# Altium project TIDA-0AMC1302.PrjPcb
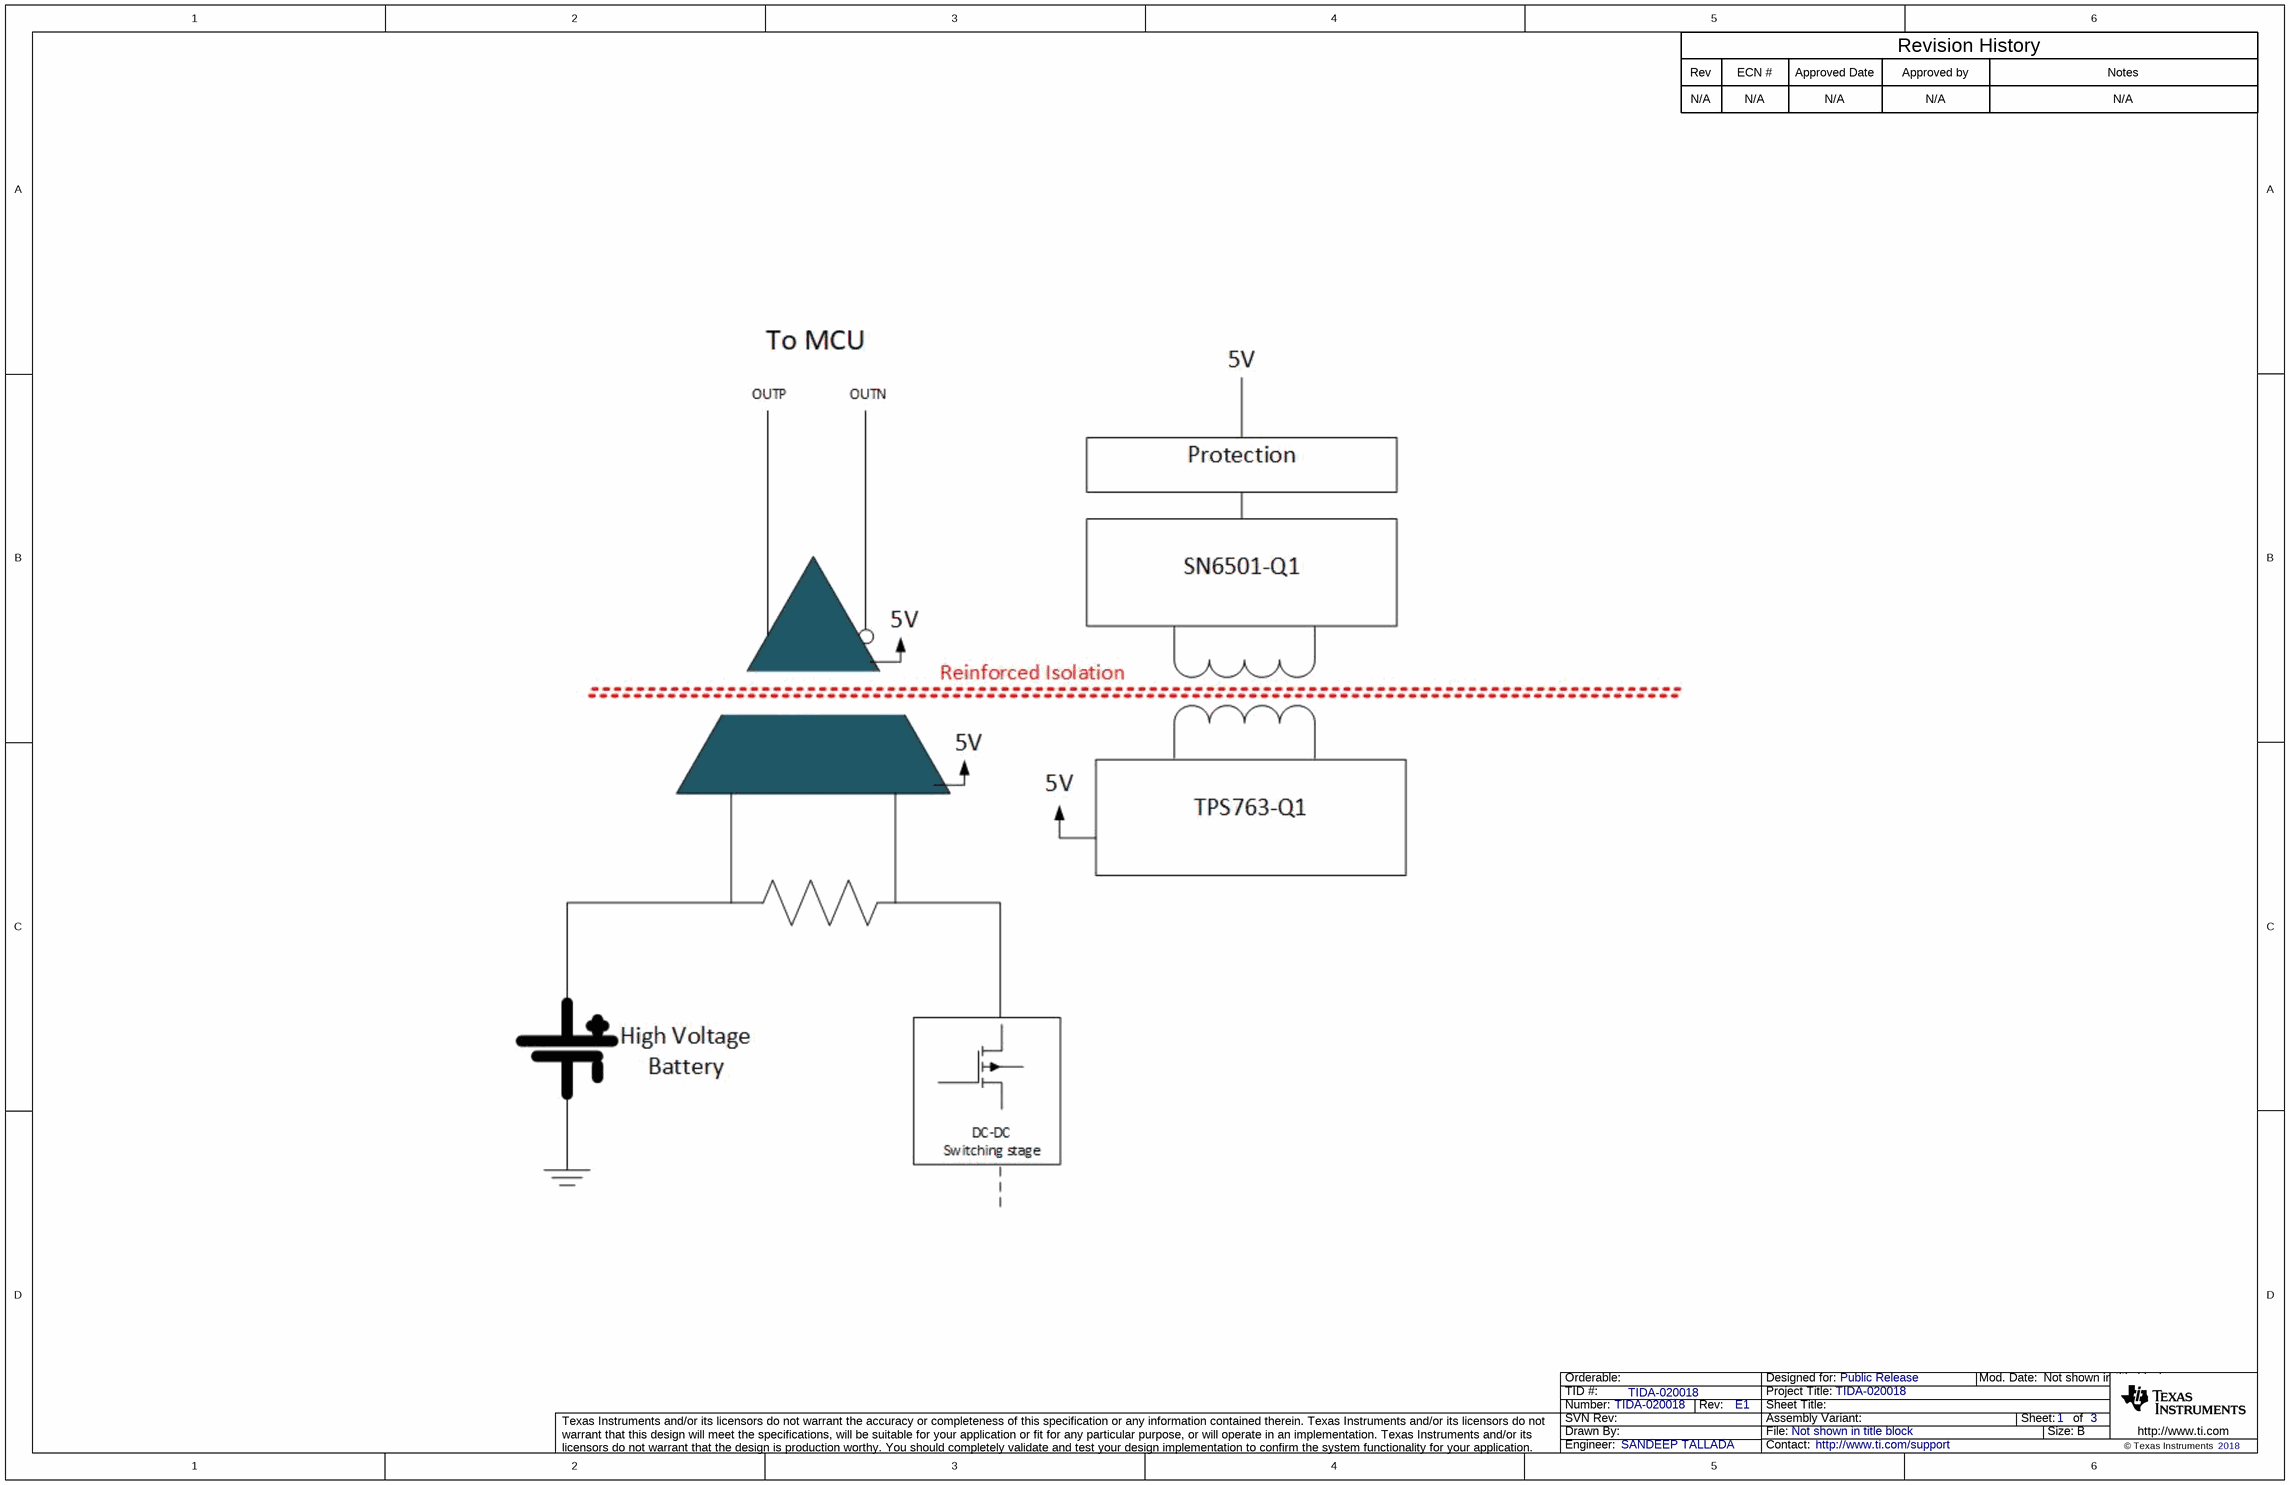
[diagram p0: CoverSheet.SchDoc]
TID: TIDA-020018; TechSupport: http://www.ti.com/support; SCH_Rev: E1; PRJ_Title: TIDA-020018; PRJ_Number: TIDA-020018; PRJ_Engineer: SANDEEP TALLADA; PRJ_Customer: Public Release; PCB_Rev: E1; PCB_Layout: Sandeep; CopyrightYear: 2018
3 sheets, 64 parts. Net scope: flat (ports and power ports of the same name join across sheets).
Board file: TIDA-0AMC1302.PcbDoc
Sheets:
  CoverSheet.SchDoc
  BlankSheet.SchDoc
  EVM_Hardware.SchDoc

## Sheet CoverSheet.SchDoc
size 431 x 279 mm; Date: Not shown in title block; ApprovedBy: Not shown in title block; CheckedBy: Not shown in title block; Author: Not shown in title block; CompanyName: Not shown in title block; Engineer: Not shown in title block; Organization: Not shown in title block; Address1: Not shown in title block; Address2: Not shown in title block; Address3: Not shown in title block; Address4: Not shown in title block; DocumentNumber: 1; Revision: Use project parameter SCH_Rev; SheetNumber: 1; SheetTotal: 3; PageSetup: Record=PageOptions¦CenterHorizontal=True¦CenterVertical=True¦PrintScale=1.00¦XCorrection=1.00¦YCorrection=1.00¦PrintKind=0¦BorderSize=5000000¦LeftOffset=0¦BottomOffset=0¦Orientation=2¦PaperLength=1000¦PaperWidth=1000¦Scale=100¦PaperSource=15¦PrintQuality=600¦MediaType=1¦DitherType=10¦PaperKind=Letter¦PrintScaleMode=1

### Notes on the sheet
- Rev
- N/A
- ECN #
- Approved Date
- Approved by
- Revision History
- Notes

## Sheet BlankSheet.SchDoc: TIDA-020018
size 431 x 279 mm; Date: Not shown in title block; ApprovedBy: Not shown in title block; CheckedBy: Not shown in title block; Author: Not shown in title block; CompanyName: Not shown in title block; Engineer: Sandeep Tallada; Organization: Not shown in title block; Address1: Not shown in title block; Address2: Not shown in title block; Address3: Not shown in title block; Address4: Not shown in title block; DocumentNumber: 1; Revision: Use project parameter SCH_Rev; SheetNumber: 2; SheetTotal: 3; PageSetup: Record=PageOptions¦CenterHorizontal=True¦CenterVertical=True¦PrintScale=1.00¦XCorrection=1.00¦YCorrection=1.00¦PrintKind=0¦BorderSize=5000000¦LeftOffset=0¦BottomOffset=0¦Orientation=2¦PaperLength=1000¦PaperWidth=1000¦Scale=100¦PaperSource=15¦PrintQuality=600¦MediaType=1¦DitherType=10¦PaperKind=Letter¦PrintScaleMode=1
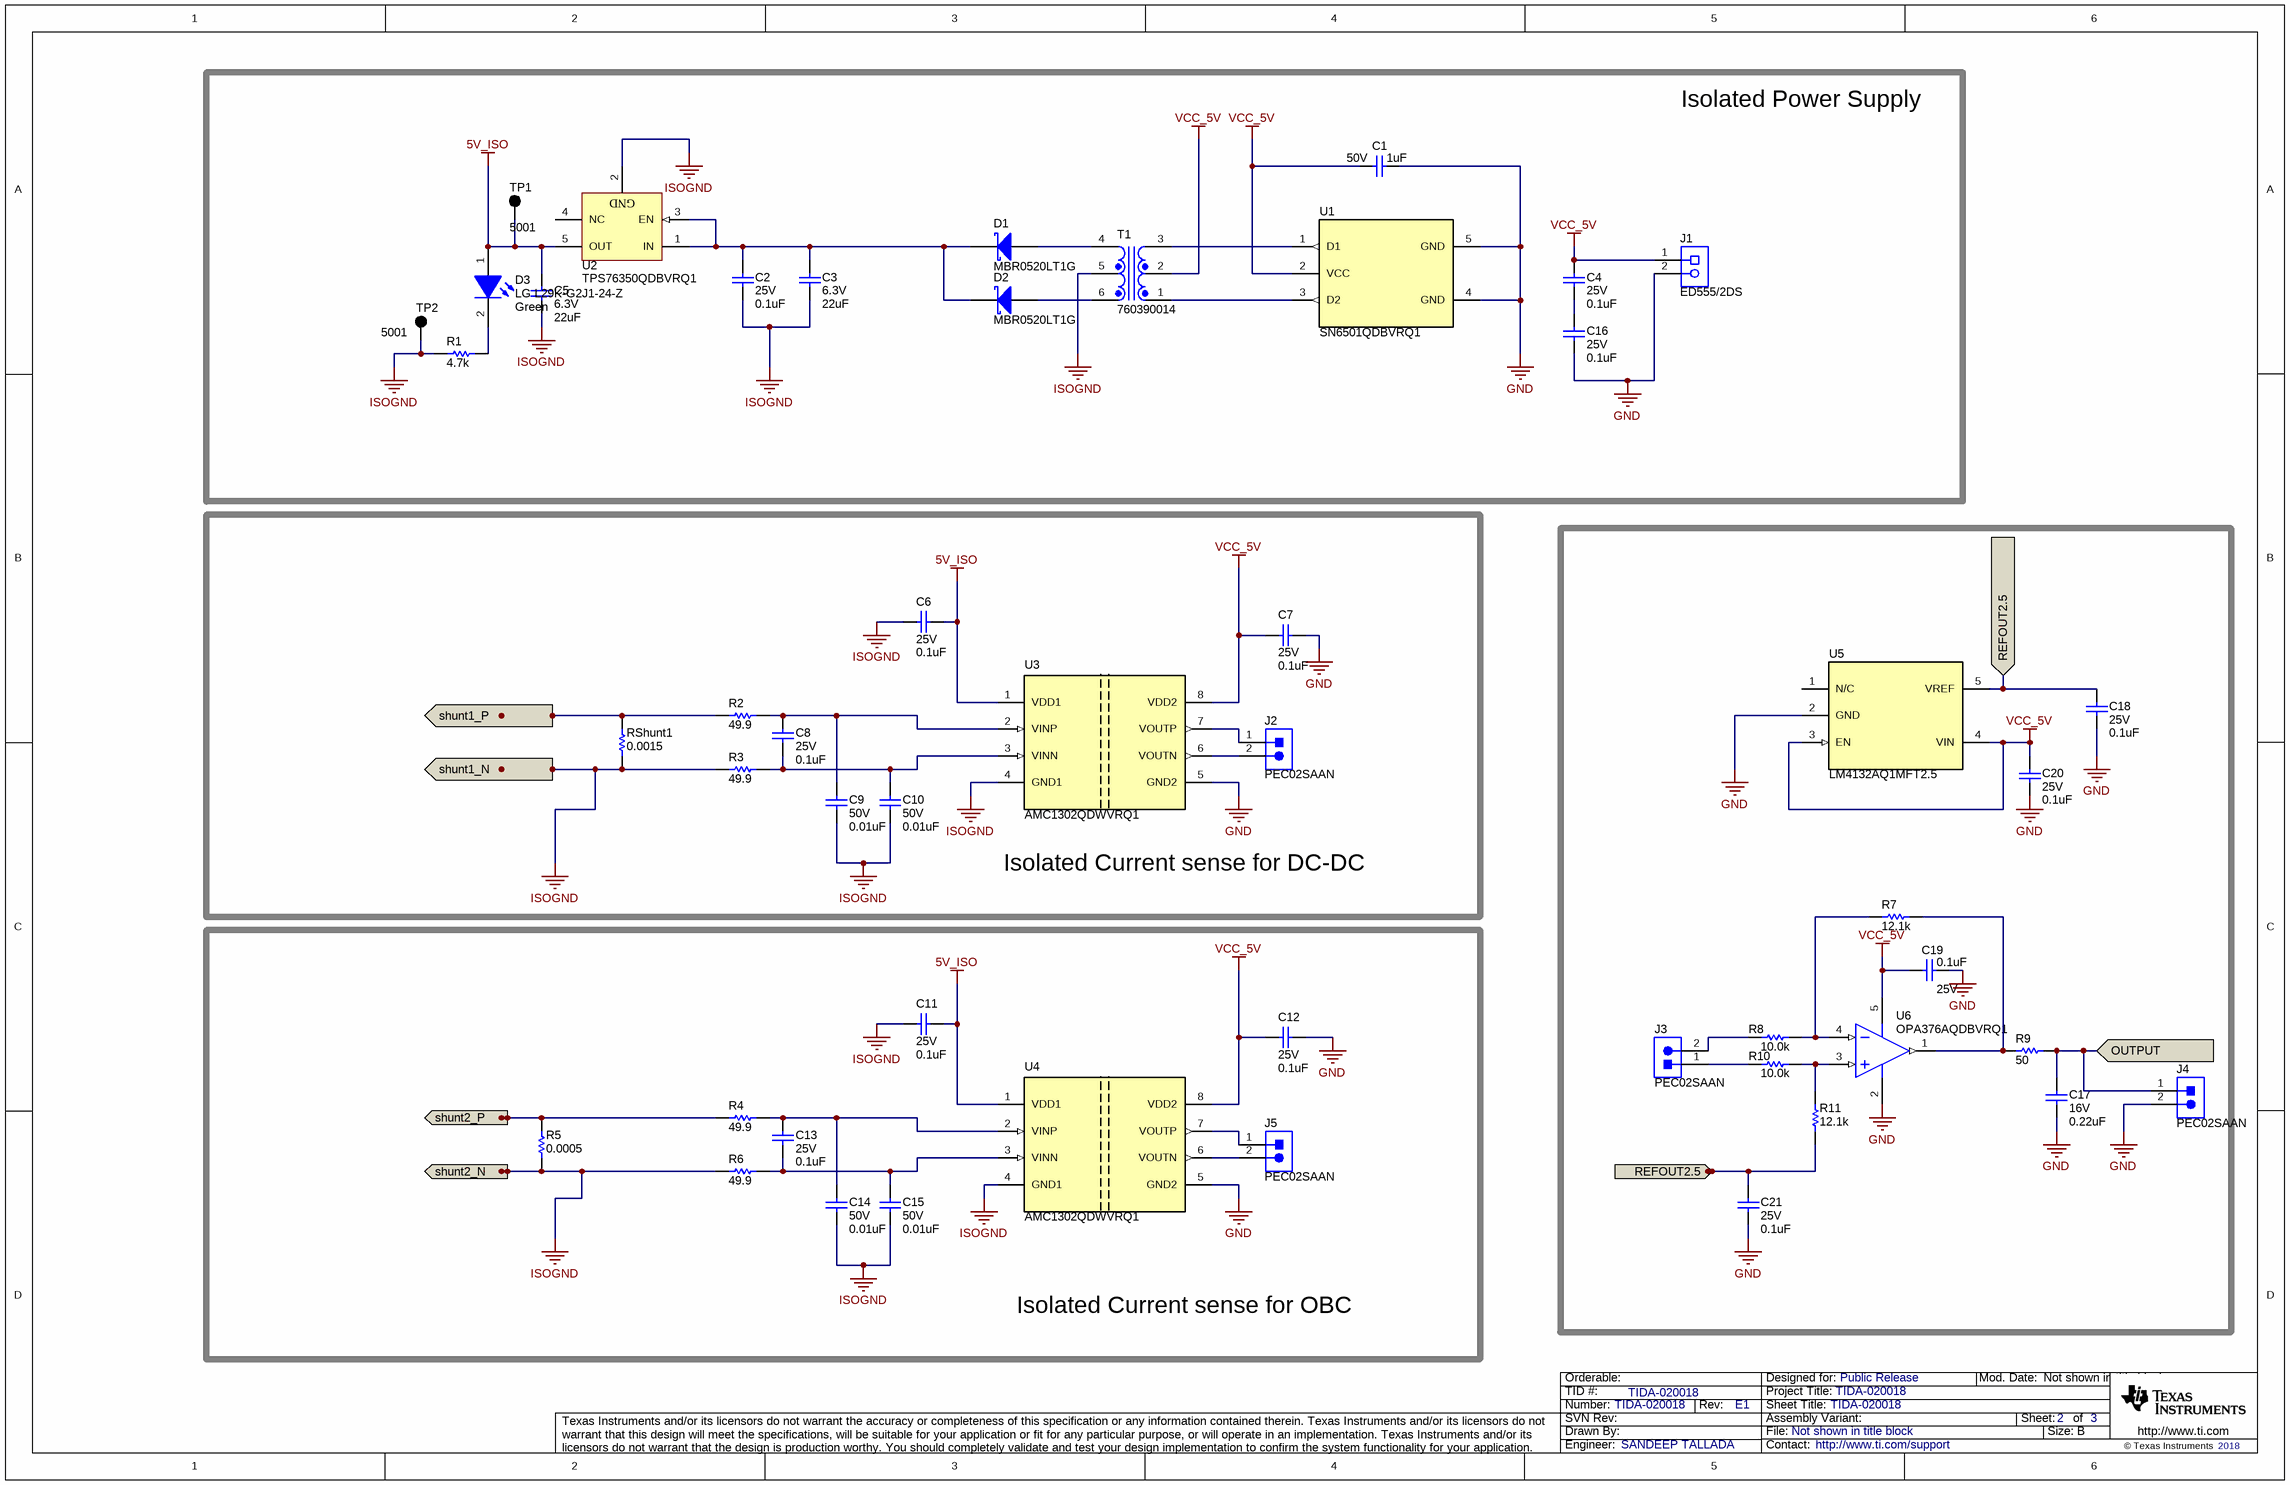
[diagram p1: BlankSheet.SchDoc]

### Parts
C1  VDC_V: 50V  ValueDisplayed: 1uF  [0603]  (hidden comment: UMK107AB7105KA-T)
C2  VDC_V: 25V  ValueDisplayed: 0.1uF  [0603]  (hidden comment: C1608X7R1E104K080AA)
C3  VDC_V: 6.3V  ValueDisplayed: 22uF  [0805_HV]  (hidden comment: JMK212BJ226MG-T)
C4  VDC_V: 25V  ValueDisplayed: 0.1uF  [0603]  (hidden comment: C1608X7R1E104K080AA)
C5  VDC_V: 6.3V  ValueDisplayed: 22uF  [0805_HV]  (hidden comment: JMK212BJ226MG-T)
C6  VDC_V: 25V  ValueDisplayed: 0.1uF  [0603]  (hidden comment: C1608X7R1E104K080AA)
C7  VDC_V: 25V  ValueDisplayed: 0.1uF  [0603]  (hidden comment: C1608X7R1E104K080AA)
C8  VDC_V: 25V  ValueDisplayed: 0.1uF  [0603]  (hidden comment: C1608X7R1E104K080AA)
C9  VDC_V: 50V  ValueDisplayed: 0.01uF  [0603]  (hidden comment: CL10B103KB8NCNC)
C10  VDC_V: 50V  ValueDisplayed: 0.01uF  [0603]  (hidden comment: CL10B103KB8NCNC)
C11  VDC_V: 25V  ValueDisplayed: 0.1uF  [0603]  (hidden comment: C1608X7R1E104K080AA)
C12  VDC_V: 25V  ValueDisplayed: 0.1uF  [0603]  (hidden comment: C1608X7R1E104K080AA)
C13  VDC_V: 25V  ValueDisplayed: 0.1uF  [0603]  (hidden comment: C1608X7R1E104K080AA)
C14  VDC_V: 50V  ValueDisplayed: 0.01uF  [0603]  (hidden comment: CL10B103KB8NCNC)
C15  VDC_V: 50V  ValueDisplayed: 0.01uF  [0603]  (hidden comment: CL10B103KB8NCNC)
C16  VDC_V: 25V  ValueDisplayed: 0.1uF  [0603]  (hidden comment: C1608X7R1E104K080AA)
C17  VDC_V: 16V  ValueDisplayed: 0.22uF  [0402]  (hidden comment: C1005X7R1C224K050BC)
C18  VDC_V: 25V  ValueDisplayed: 0.1uF  [0603]  (hidden comment: C1608X7R1E104K080AA)
C19  VDC_V: 25V  ValueDisplayed: 0.1uF  [0603]  (hidden comment: C1608X7R1E104K080AA)
C20  VDC_V: 25V  ValueDisplayed: 0.1uF  [0603]  (hidden comment: C1608X7R1E104K080AA)
C21  VDC_V: 25V  ValueDisplayed: 0.1uF  [0603]  (hidden comment: C1608X7R1E104K080AA)
D1  MBR0520LT1G  [SOD-123]
D2  MBR0520LT1G  [SOD-123]
D3  LG L29K-G2J1-24-Z  value Green  [LG L29K_GREEN]
J1  ED555/2DS  [TERM_BLK_ED555-2DS]
J2  PEC02SAAN  [CONN_PEC02SAAN]
J3  PEC02SAAN  [CONN_PEC02SAAN]
J4  PEC02SAAN  [CONN_PEC02SAAN]
J5  PEC02SAAN  [CONN_PEC02SAAN]
R1  ValueDisplayed: 4.7k  [0603]  (hidden comment: CRCW06034K70JNEA)
R2  ValueDisplayed: 49.9  [TNPW0603]  (hidden comment: TNPW060349R9BEEA)
R3  ValueDisplayed: 49.9  [TNPW0603]  (hidden comment: TNPW060349R9BEEA)
R4  ValueDisplayed: 49.9  [TNPW0603]  (hidden comment: TNPW060349R9BEEA)
R5  ValueDisplayed: 0.0005  [CSS2725_0005]  (hidden comment: CSS2725FTL500)
R6  ValueDisplayed: 49.9  [TNPW0603]  (hidden comment: TNPW060349R9BEEA)
R7  ValueDisplayed: 12.1k  [0402]  (hidden comment: ERA-2AEB1212X)
R8  ValueDisplayed: 10.0k  [0402]  (hidden comment: RT0402BRD0710KL)
R9  ValueDisplayed: 50  [0402]  (hidden comment: FC0402E50R0BST1)
R10  ValueDisplayed: 10.0k  [0402]  (hidden comment: RT0402BRD0710KL)
R11  ValueDisplayed: 12.1k  [0402]  (hidden comment: ERA-2AEB1212X)
RShunt1  ValueDisplayed: 0.0015  [2512_WIDE]  (hidden comment: PML100HZPJV1L5)
T1  760390014  [Wurth_760390013]
TP1  5001  [Keystone5001]
TP2  5001  [Keystone5001]
U1  SN6501QDBVRQ1  [DBV0005A_L]
U2  TPS76350QDBVRQ1  [DBV0005A_N]
U3  AMC1302QDWVRQ1  [DWV0008A]
U4  AMC1302QDWVRQ1  [DWV0008A]
U5  LM4132AQ1MFT2.5  [DBV0005A_N]
U6  OPA376AQDBVRQ1  [DBV0005A_N]

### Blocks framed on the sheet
Isolated Power Supply: C1-C5 C16 D1-D3 J1 R1 T1 TP1 TP2 U1 U2
Isolated Current sense for DC-DC: C6-C10 J2 R2 R3 RShunt1 U3
Isolated Current sense for OBC: C11-C15 J5 R4-R6 U4

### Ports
OUTPUT, REFOUT2.5, shunt1_N (in), shunt1_P (in), shunt2_N (in), shunt2_P (in)

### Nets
5V_ISO: C5.1 C6.2 C11.2 D3.1(A) TP1.1 U2.5(OUT) U3.1(VDD1) U4.1(VDD1)
GND: C1.1 C7.2 C12.2 C16.2 C17.2 C18.2 C19.1 C20.1 C21.2 J1.2 J4.2 U1.4(GND) U1.5(GND) U3.5(GND2) U4.5(GND2) U5.2(GND) U6.2(V-)
ISOGND: C2.2 C3.2 C5.2 C6.1 C9.2 C10.2 C11.1 C14.2 C15.2 R1.1 R3.1 R5.1 R6.1 RShunt1.1 T1.5 TP2.1 U2.2(GND) U3.4(GND1) U4.4(GND1) ; port shunt1_N, port shunt2_N
VCC_5V: C1.2 C4.1 C7.1 C12.1 C19.2 C20.2 J1.1 T1.2 U1.2(VCC) U3.8(VDD2) U4.8(VDD2) U5.3(EN) U5.4(VIN) U6.5(V+)
OUTPUT: C17.1 J4.1 R9.2 ; port OUTPUT
REFOUT2.5: C18.1 C21.1 R11.1 U5.5(VREF) ; port REFOUT2.5
shunt1_P: R2.1 RShunt1.2 ; port shunt1_P
shunt2_P: R4.1 R5.2 ; port shunt2_P
NetC2_1: C2.1 C3.1 D1.1(K) D2.1(K) U2.1(IN) U2.3(EN)
NetC4_2: C4.2 C16.1
NetC8_1: C8.1 C9.1 R2.2 U3.2(VINP)
NetC8_2: C8.2 C10.1 R3.2 U3.3(VINN)
NetC13_1: C13.1 C14.1 R4.2 U4.2(VINP)
NetC13_2: C13.2 C15.1 R6.2 U4.3(VINN)
NetD1_2: D1.2(A) T1.4
NetD2_2: D2.2(A) T1.6
NetD3_2: D3.2(K) R1.2
NetJ2_1: J2.1 U3.7(VOUTP)
NetJ2_2: J2.2 U3.6(VOUTN)
NetJ3_1: J3.1 R10.1
NetJ3_2: J3.2 R8.1
NetJ5_1: J5.1 U4.7(VOUTP)
NetJ5_2: J5.2 U4.6(VOUTN)
NetR7_1: R7.1 R8.2 U6.4(IN-)
NetR7_2: R7.2 R9.1 U6.1(OUT)
NetR10_2: R10.2 R11.2 U6.3(IN+)
NetT1_1: T1.1 U1.3(D2)
NetT1_3: T1.3 U1.1(D1)

Not connected (* = marked no-connect by the designer): U2 4(NC); U5 1(N/C)

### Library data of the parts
C1 = CMP-0007508-5: CAP, CERM, 1 uF, 50 V, +/- 10%, X7R, 0603; Manufacturer: Taiyo Yuden; TaMin_C: -55°C; Polarized: N; SizeAreaWB_mm2: 4.68; Value1: Unknown; U/M: EA; Value: 1uF; TaMax_C: 125°C; SizeZ_mm: 1; SizeX_mm: 1.6; SizeY_mm: 0.8; SizeArea_mm2: 1.28; Cap_F: 1µF; AEC Category: Q200
C2 C4 C6-C8 C11-C13 C16 C18-C21 = CMP-0007039-5: CAP, CERM, 0.1 uF, 25 V, +/- 10%, X7R, 0603; Manufacturer: TDK; TaMin_C: -55°C; Polarized: N; SizeAreaWB_mm2: 4.68; Value1: Unknown; U/M: EA; Value: 0.1uF; TaMax_C: 125°C; SizeZ_mm: 1; SizeX_mm: 1.6; SizeY_mm: 0.8; SizeArea_mm2: 1.28; Cap_F: 100nF; AEC Category: Q200
C3 C5 = CMP-0008391-2: CAP, CERM, 22 uF, 6.3 V, +/- 20%, X5R, 0805; Manufacturer: Taiyo Yuden; TaMin_C: -55°C; Polarized: N; SizeAreaWB_mm2: 6.75; Value1: Unknown; U/M: EA; Value: 22uF; TaMax_C: 85°C; SizeZ_mm: 1.45; SizeX_mm: 2; SizeY_mm: 1.25; Cap_Case: 0805; SizeArea_mm2: 2.5; Cap_F: 22µF; AEC Category: Q200
C9 C10 C14 = CMP-0007109-5: CAP, CERM, 0.01 uF, 50 V, +/- 10%, X7R, 0603; Manufacturer: Samsung Electro-Mechanics; TaMin_C: -55°C; Polarized: N; SizeAreaWB_mm2: 4.68; Value1: Unknown; U/M: EA; Value: 0.01uF; TaMax_C: 125°C; SizeZ_mm: 1; SizeX_mm: 1.6; SizeY_mm: 0.8; SizeArea_mm2: 1.28; Cap_F: 10nF; AEC Category: Q200
C15 = CMP-0007109-5: CAP, CERM, 0.01 uF, 50 V, +/- 10%, X7R, 0603; Manufacturer: Samsung Electro-Mechanics; TaMin_C: -55°C; Polarized: N; SizeAreaWB_mm2: 4.68; Value1: Unknown; U/M: EA; Value: 0.01uF; TaMax_C: 125°C; SizeZ_mm: 1; SizeX_mm: 1.6; SizeY_mm: 0.8; SizeArea_mm2: 1.28; CompType: Capacitor; Cap_F: 10nF; AEC Category: Q200
C17 = CMP-0006293-2: CAP, CERM, 0.22 uF, 16 V, +/- 10%, X7R, 0402; Manufacturer: TDK; TaMin_C: -55°C; Polarized: N; SizeAreaWB_mm2: 3; Value1: Unknown; U/M: EA; Value: 0.22uF; TaMax_C: 125°C; SizeZ_mm: 0.6; SizeX_mm: 1; SizeY_mm: 0.5; Cap_F: 220nF; AEC Category: Q200
D1 D2 = CMP-0028524-1: Diode, Schottky, 20 V, 0.5 A, SOD-123; Manufacturer: ON Semiconductor; Io_A: 5dA; Green_Lifecycle: Active; SizeAreaWB_mm2: 13.095; Vr_V: 20V; Green_REACh: Passed; Value1: 0.5A; TJmax_C: 125°C; U/M: EA; Value: 20V; SizeZ_mm: 1.35; SizeX_mm: 3.85; SizeY_mm: 1.7; Vf_V: 3.85dV; Value2: 0.385V; SizeArea_mm2: 6.545; AEC Category: Q101; RJC_CperW: 150
D3 = CMP-0002874-1: LED, Green, SMD; Manufacturer: OSRAM; Io_A: 2mA; Tjmax_C: 110°C; Value1: W; U/M: EA; Vf_V: 1.7V
J1 = CMP-0074913-1: Terminal Block, 3.5mm Pitch, 2x1, TH; Manufacturer: On-Shore Technology; Cert_VDE: Y; CNHeader: False; Current_A: 6A; Green_Lifecycle: Active; Shrouded: N; Gender: Female; Green_REACh: Passed; Voltage_V: 150V; Row_Count: 1; Pitch_mm: 3.5; ContactFinish: Brass; CT: True
J2-J5 = CMP-0002337-1: Header, 100mil, 2x1, Tin, TH; Manufacturer: Sullins Connector Solutions; CNHeader: TRUE; Current_A: 3A; Green_Lifecycle: Not Set; Shrouded: N; Gender: Male; Green_REACh: Incomplete; Voltage_V: 1.8kV; Row_Count: 1; Pitch_mm: 2.54; CT: FALSE; Cert_UL: Y
R1 = CMP-0025817-4: RES, 4.7 k, 5%, 0.1 W, AEC-Q200 Grade 0, 0603; Manufacturer: Vishay-Dale; Power_W: 100mW; TempCo: 200 ppm/C; Value_Code: 4k70; Value: 4.7k; EIA_Code: E24; SizeX_mm: 1.6; SizeY_mm: 0.8; SizeZ_mm: 1; Value2: 0.1W; SizeArea_mm2: 1.28; AEC Qualified: Y; VDC_V: 75V; AEC Category: Q200; AEC Grade: 0
R2-R4 R6 = CMP-0025693-1: RES, 49.9, 0.1%, 0.1 W, AEC-Q200 Grade 1, 0603; Manufacturer: Vishay-Dale; Power_W: 100mW; TempCo: 25 ppm/C; Value_Code: 49R9; U/M: EA; Value: 49.9; EIA_Code: E192; SizeX_mm: 1.6; SizeY_mm: 0.85; SizeZ_mm: 0.55; Value2: 0.1W; SizeArea_mm2: 1.36; AEC Qualified: Y; VDC_V: 75V; AEC Grade: 1; AEC Category: Q200
R5 = CMP-0015026-2: RES, 0.0005, 1%, 4 W, RES_2725; Manufacturer: Stackpole Electronics Inc; Power_W: 4W; TempCo: 50 ppm/C; Value_Code: L5000; U/M: EA; Value: 0.0005; Res_ohm: 500µ; AEC Category: Q200
R7 R11 = CMP-0083631-1: RES, 12.1 k, 0.1%, 0.063 W, AEC-Q200 Grade 0, 0402; Manufacturer: Panasonic; Power_W: 63mW; TempCo: 25 ppm/C; SizeAreaWB_mm2: 3; Value_Code: 12k1; Value: 12.1k; EIA_Code: E192; SizeX_mm: 1; SizeY_mm: 0.5; SizeZ_mm: 0.6; Value2: 0.063W; AEC Qualified: Y; VDC_V: 50V; AEC Grade: 0; AEC Category: Q200
R8 R10 = CMP-0065360-1: RES, 10.0 k, .1%, .0625 W, 0402; Manufacturer: Yageo America; Power_W: 62.5mW; TempCo: 25 ppm/C; Value_Code: 10k0; U/M: EA; Value: 10.0k; EIA_Code: E192; Tolerance_%: 0.1%; Res_ohm: 10k; SizeX_mm: 1.0; SizeY_mm: 0.5; SizeZ_mm: 0.6; Value2: .0625W; VDC_V: 50V; AEC Category: Q200
R9 = CMP-0026791-1: RES, 50, 0.1%, 0.05 W, 0402; Manufacturer: Vishay-Dale; Power_W: 50mW; TempCo: 25 ppm/C; Value_Code: 50R0; U/M: EA; Value: 50; SizeX_mm: 1; SizeY_mm: 0.5; SizeZ_mm: 0.6; Value2: 0.05W; AEC Qualified: N; AEC Category: Q200
RShunt1 = CMP-0084409-1: RES, 0.0015, 5%, 2 W, 2512 WIDE; Manufacturer: Rohm; Value_Code: 1L500; Res_ohm: 1.5m; AEC Qualified: N; Value: 0.0015; SizeArea_mm2: 20.16; SizeY_mm: 6.3; SizeAreaWB_mm2: 43.16; AEC Category: Q200; Power_W: 2W; SizeX_mm: 3.2; TempCo: 100 ppm/C; SizeZ_mm: 0.7
T1 = CMP-0030718-1: Transformer, 475uH, SMT; Manufacturer: Wurth Elektronik; DCR_ohm: 3.1d; Lp: 475; Ind_H: 475µH
TP1 TP2 = CMP-0055138-1: Test Point, Miniature, Black, TH; Manufacturer: Keystone; CNHeader: FALSE; Green_Lifecycle: Active; Green_REACh: Passed; ContactFinish: Silver; CT: TRUE
U1 = CMP-0076093-1: Automotive Low-Noise 350 mA, 410 kHz Transformer Driver, DBV0005A (SOT-23-5); Manufacturer: Texas Instruments; SizeAreaWB_mm2: 14.82; SizeArea_mm2: 8.12; SizeZ_mm: 1.45; SizeY_mm: 2.9; U/M: EA; CompType: IC; SizeX_mm: 2.8
U2 = CMP-0035574-1: Single Output Automotive LDO, 150 mA, Fixed 5 V Output, 2.7 to 10 V Input, 5-pin SOT-23 (DBV), -40 to 125 degC, Green (RoHS & no Sb/Br); Manufacturer: Texas Instruments; Vout Adj(Min)(V): 5; Vin(Min)(V): 2.7; Vin(Max)(V): 10; SubFamily: Single Channel LDO; Vdo(Typ)(mV): 300; Fixed Output Options(V): 5.0; Accuracy(%): 3; Iq(Typ)(mA): 0.08; Iout(Max)(A): 0.15
U3 U4 = CMP-0080587-1: Precision Reinforced Isolated Amplifier for Current Sensing, DWV0008A (SOIC-8); Alternate Manufacturer: Texas Instruments; SizeAreaWB_mm2: 105.975; SizeZ_mm: 2.8; SizeX_mm: 11.5; SizeY_mm: 5.85; SizeArea_mm2: 67.275; CompType: IC; AEC Qualified: Y; AEC Category: Q200
U5 = CMP-0081400-1: Automotive SOT23 Precision Low Dropout Voltage Reference, DBV0005A (SOT-23-5); Alternate PartNumber: LM4132AQ1MFR2.5; Alternate Manufacturer: Texas Instruments; SizeAreaWB_mm2: 14.82; SizeZ_mm: 1.45; SizeX_mm: 2.8; SizeY_mm: 2.9; SizeArea_mm2: 8.12; CompType: IC; AEC Qualified: Y; AEC Category: Q200
U6 = CMP-0041022-2: Automotive Catalog Precision, Low Noise, Low Iq Operational Amplifier, 2.2 to 5.5 V, -40 to 125 degC, 5-pin SOT23 (DBV5), Green (RoHS & no Sb/Br); Manufacturer: Texas Instruments; Sub Family: Low Input Bias Current Amp (<=10pA), Low Noise Amp (<=10nV/rtHz), Low Offset Voltage Amplifier (<=500uV), Low Supply Voltage Amplifier (<=2.7V), Precision Amplifier; Total Supply Voltage(Min)(+5V is 5, +/-5V is 10): 2.2; Slew Rate(Typ)(V/us): 2; Vio (25C)(Max)(mV): 0.025; Total Supply Voltage(Max)(+5V is 5, +/-5V is 10): 5.5; IIB(Max)(pA): 10; Offset Drift(Typ)(uV/C): 0.32; Iq per channel(Max)(mA): 0.95; CMRR(Min)(dB): 76; Number of Channels: 1; Vn at 1kHz(Typ)(nV/rtHz): 7.5

## Sheet EVM_Hardware.SchDoc
size 431 x 279 mm; Date: Not shown in title block; ApprovedBy: Not shown in title block; CheckedBy: Not shown in title block; Author: Not shown in title block; CompanyName: Not shown in title block; Engineer: Not shown in title block; Organization: Not shown in title block; Address1: Not shown in title block; Address2: Not shown in title block; Address3: Not shown in title block; Address4: Not shown in title block; DocumentNumber: 1; Revision: Use project parameter SCH_Rev; SheetNumber: 3; SheetTotal: 3; PageSetup: Record=PageOptions¦CenterHorizontal=True¦CenterVertical=True¦PrintScale=1.00¦XCorrection=1.00¦YCorrection=1.00¦PrintKind=0¦BorderSize=5000000¦LeftOffset=0¦BottomOffset=0¦Orientation=2¦PaperLength=1000¦PaperWidth=1000¦Scale=100¦PaperSource=15¦PrintQuality=600¦MediaType=1¦DitherType=10¦PaperKind=Letter¦PrintScaleMode=1
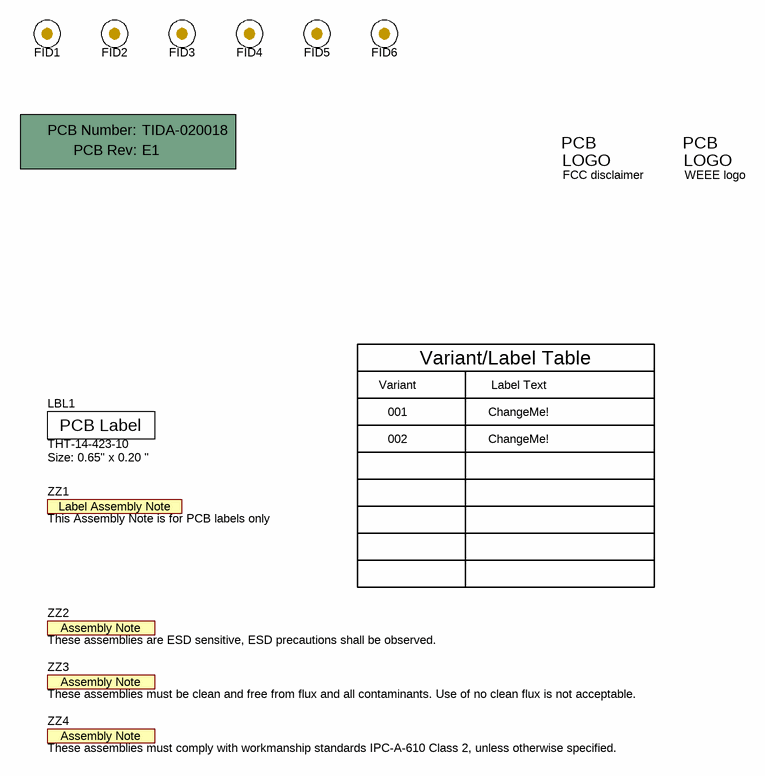
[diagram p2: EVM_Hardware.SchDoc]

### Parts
!PCB1  Printed Circuit Board  (value not drawn)  (mechanical)
FID1  Fiducial  [Fiducial10-20]  (value not drawn)
FID2  Fiducial  [Fiducial10-20]  (value not drawn)
FID3  Fiducial  [Fiducial10-20]  (value not drawn)
FID4  Fiducial  [Fiducial10-20]  (value not drawn)
FID5  Fiducial  [Fiducial10-20]  (value not drawn)
FID6  Fiducial  [Fiducial10-20]  (value not drawn)
LBL1  THT-14-423-10  Note: Size: 0.65" x 0.20 "  [Label_650x200]
Logo3  FCC disclaimer  [FCC_disclaimer]  (no BOM)
Logo4  WEEE logo  [WEEE_Minimum]  (no BOM)
ZZ1  This Assembly Note is for PCB labels only  [AssemblyNoteLabel]  (no BOM)
ZZ2  These assemblies are ESD sensitive, ESD precautions shall be observed.  [AssemblyNote]  (no BOM)
ZZ3  These assemblies must be clean and free from flux and all contaminants. Use of no clean flux is not acceptable.  [AssemblyNote]  (no BOM)
ZZ4  These assemblies must comply with workmanship standards IPC-A-610 Class 2, unless otherwise specified.  [AssemblyNote]  (no BOM)

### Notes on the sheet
- Variant
- Variant/Label Table
- Label Text
- 001
- 002
- ChangeMe!

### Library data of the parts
!PCB1 = CMP-0003618-2: Manufacturer: Any; PartNumber: TIDA-020018
FID1-FID6 = CMP-0077181-1: Fiducial mark.  There is nothing to buy or mount.
LBL1 = CMP-0003625-1: Thermal Transfer Printable Labels, 0.650" W x 0.200" H - 10,000 per roll; Manufacturer: Brady; CompType: Label
Logo3 = CMP-0074847-1: FCC_disclaimer; Library Reference: Logo
Logo4 = CMP-0074769-1
ZZ1 = CMP-0003616-3
ZZ2 = CMP-0077236-1
ZZ3 = CMP-0077237-1
ZZ4 = CMP-0077238-1

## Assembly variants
001: not fitted FID1 FID2 FID3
